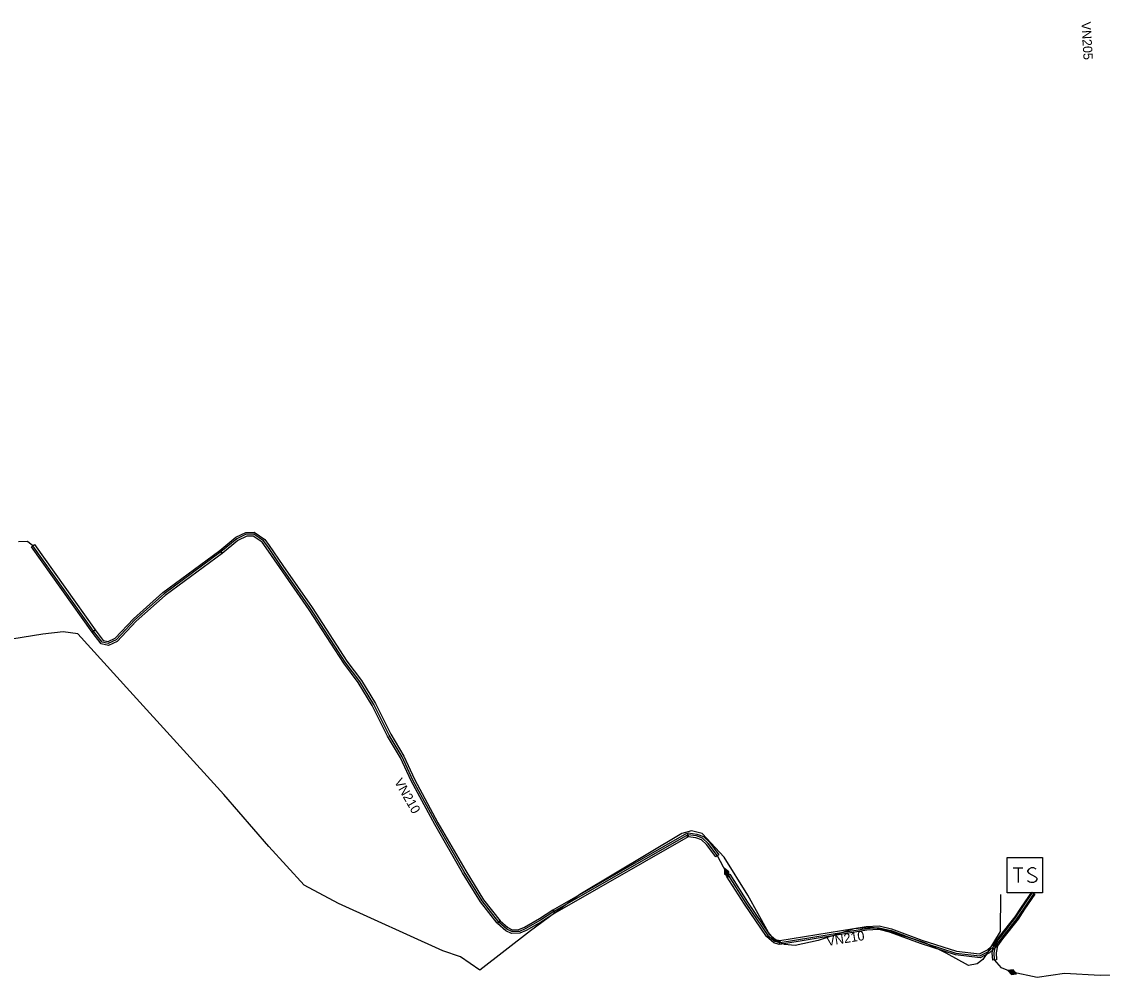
# Model space of a CAD drawing. Extents: x -643811 to -636362, y -1117362 to -1108614.
# Drawn here: x -641784.1 to -641668.7, y -1114810.2 to -1114708.1 of the extents above; entities that cross this region are included whole.
import ezdxf

# ---------------------------------------------------------------- set-up
doc = ezdxf.new("R2010")
doc.units = 0
for name, color, linetype in [('19', 7, 'Continuous'), ('20', 7, 'Continuous'), ('25', 7, 'Continuous'), ('5', 7, 'Continuous'), ('7', 7, 'Continuous'), ('9', 7, 'Continuous')]:
    doc.layers.add(name, color=color, linetype=linetype)

# ---------------------------------------------------------------- blocks, each defined once
blk = doc.blocks.new('VN870')
at = {"layer": '19'}
for points in [[(0, -0.25), (0.5, 0), (0, 0.25), (-0.5, 0), (0, -0.25)], [(0.37, 0), (0, 0.19), (-0.36, 0), (0, -0.19), (0.37, 0)], [(0.24, 0), (0, 0.12), (-0.25, 0), (0, -0.12), (0.24, 0)], [(0.12, 0), (0, 0.06), (-0.13, 0), (0, -0.06), (0.12, 0)]]:
    blk.add_lwpolyline(points, dxfattribs=at)
blk = doc.blocks.new('VN640')
at = {"layer": '25'}
for points in [[(-1.89, 1.89), (1.89, 1.89)], [(-1.89, -1.89), (-1.89, 1.89)], [(1.89, 1.89), (1.89, -1.89)], [(-1.26, 0.79), (-0.22, 0.79)], [(-0.73, 0.79), (-0.73, -0.79)], [(1.2, 0.66), (0.94, 0.79), (0.66, 0.79), (0.41, 0.66), (0.28, 0.47), (0.28, 0.41), (0.41, 0.22), (1.13, -0.16), (1.26, -0.32), (1.26, -0.47), (1.13, -0.66), (0.91, -0.79), (0.63, -0.79), (0.5, -0.73), (0.28, -0.6)], [(1.89, -1.89), (-1.89, -1.89)]]:
    blk.add_lwpolyline(points, dxfattribs=at)

msp = doc.modelspace()

# ---------------------------------------------------------------- linework, layer by layer
at = {"layer": '20'}
for points in [[(-641762.97, -1114764.61), (-641761.25, -1114763.21), (-641760.19, -1114762.69), (-641759.29, -1114762.68), (-641758.16, -1114763.45), (-641757.68, -1114764.09), (-641756.24, -1114766.23), (-641753.1, -1114770.73), (-641749.4, -1114776.45), (-641747.84, -1114778.5), (-641746.34, -1114780.98), (-641744.69, -1114784.26), (-641743.31, -1114786.6), (-641742.18, -1114789.07), (-641739.66, -1114793.71), (-641736.7, -1114798.85), (-641734.79, -1114801.95), (-641733.02, -1114804.19), (-641733.01, -1114804.21), (-641733.17, -1114804.33), (-641733.33, -1114804.45), (-641735.11, -1114802.17), (-641737.04, -1114799.05), (-641740, -1114793.91), (-641742.54, -1114789.25), (-641743.67, -1114786.78), (-641745.05, -1114784.46), (-641746.7, -1114781.18), (-641748.18, -1114778.72), (-641749.72, -1114776.68), (-641753.44, -1114770.95), (-641756.56, -1114766.45), (-641758, -1114764.33), (-641758.44, -1114763.75), (-641759.41, -1114763.08), (-641760.09, -1114763.09), (-641761.03, -1114763.55), (-641762.72, -1114764.93), (-641762.85, -1114764.77), (-641762.98, -1114764.61)], [(-641776.46, -1114773.24), (-641776.62, -1114773.36), (-641783.1, -1114764.23), (-641782.78, -1114763.99), (-641776.3, -1114773.12), (-641776.3, -1114773.12)], [(-641762.97, -1114764.61), (-641762.97, -1114764.61), (-641762.85, -1114764.77), (-641762.73, -1114764.93), (-641768.8, -1114769.43), (-641771.9, -1114772.19), (-641773.92, -1114774.35), (-641774.86, -1114774.77), (-641775.64, -1114774.6), (-641776.62, -1114773.36), (-641776.46, -1114773.24), (-641776.3, -1114773.12), (-641776.3, -1114773.12), (-641775.42, -1114774.24), (-641774.9, -1114774.35), (-641774.16, -1114774.01), (-641772.18, -1114771.91), (-641769.06, -1114769.11)], [(-641727.37, -1114803.02), (-641713.08, -1114794.84), (-641712.98, -1114795.01), (-641712.88, -1114795.18), (-641712.94, -1114795.22), (-641727.17, -1114803.36), (-641727.17, -1114803.36), (-641727.27, -1114803.19)], [(-641712.95, -1114794.81), (-641712.01, -1114794.93), (-641711.29, -1114795.19), (-641710.66, -1114795.79), (-641709.64, -1114797.13), (-641709.96, -1114797.37), (-641710.96, -1114796.05), (-641711.51, -1114795.53), (-641712.11, -1114795.33), (-641712.94, -1114795.22), (-641713.01, -1114795.21), (-641712.98, -1114795.01)], [(-641703.17, -1114806.52), (-641703.22, -1114806.71), (-641703.78, -1114806.55), (-641704.57, -1114805.88), (-641706.92, -1114802.41), (-641708.83, -1114799.43), (-641708.49, -1114799.21), (-641706.59, -1114802.19), (-641704.27, -1114805.61), (-641703.59, -1114806.19), (-641703.15, -1114806.31), (-641703.11, -1114806.33)], [(-641676.22, -1114801.12), (-641675.89, -1114801.34), (-641677, -1114802.96), (-641677.68, -1114804), (-641679.34, -1114806.12), (-641679.89, -1114806.85), (-641679.92, -1114806.89), (-641680.08, -1114806.77), (-641680.08, -1114806.77), (-641680.24, -1114806.65), (-641680.22, -1114806.63), (-641679.66, -1114805.88), (-641678.01, -1114803.76), (-641677.33, -1114802.74)], [(-641733.02, -1114804.19), (-641732.21, -1114804.92), (-641731.72, -1114805.14), (-641731.01, -1114805.13), (-641730.42, -1114804.88), (-641728.82, -1114803.95), (-641727.38, -1114803.02), (-641727.27, -1114803.19), (-641727.16, -1114803.36), (-641727.17, -1114803.36), (-641728.62, -1114804.29), (-641730.24, -1114805.24), (-641730.93, -1114805.53), (-641731.8, -1114805.54), (-641732.43, -1114805.26), (-641733.3, -1114804.48), (-641733.17, -1114804.33), (-641733.04, -1114804.18)], [(-641703.15, -1114806.31), (-641693.9, -1114804.8), (-641692.51, -1114804.73), (-641691.2, -1114805.05), (-641687.97, -1114806.25), (-641684.28, -1114807.44), (-641681.8, -1114807.73), (-641680.97, -1114807.29), (-641680.22, -1114806.63), (-641680.21, -1114806.62), (-641680.08, -1114806.77), (-641680.08, -1114806.77), (-641679.94, -1114806.92), (-641680.39, -1114807.31), (-641680.74, -1114807.62), (-641681.72, -1114808.14), (-641684.37, -1114807.84), (-641688.1, -1114806.63), (-641691.32, -1114805.43), (-641692.55, -1114805.13), (-641693.86, -1114805.2), (-641703.13, -1114806.72), (-641703.17, -1114806.52), (-641703.2, -1114806.32)], [(-641680.27, -1114806.73), (-641680.08, -1114806.77), (-641680.08, -1114806.77), (-641679.88, -1114806.81), (-641679.89, -1114806.85), (-641680.04, -1114807.63), (-641679.99, -1114808.35), (-641680.39, -1114808.38), (-641680.45, -1114807.61), (-641680.39, -1114807.31)]]:
    msp.add_lwpolyline(points, close=True, dxfattribs=at)
at = {"layer": '5'}
for points in [[(-641708.82, -1114799.06), (-641709.8, -1114797.25), (-641710.81, -1114795.92), (-641711.4, -1114795.36), (-641712.06, -1114795.13), (-641712.98, -1114795.01), (-641725.87, -1114802.39), (-641727.27, -1114803.19), (-641728.72, -1114804.12), (-641730.33, -1114805.06), (-641730.97, -1114805.33), (-641731.76, -1114805.34), (-641732.32, -1114805.09), (-641733.17, -1114804.33), (-641734.95, -1114802.06), (-641736.87, -1114798.95), (-641739.83, -1114793.81), (-641742.36, -1114789.16), (-641743.49, -1114786.69), (-641744.87, -1114784.36), (-641746.52, -1114781.08), (-641748.01, -1114778.61), (-641749.56, -1114776.57), (-641753.27, -1114770.84), (-641756.4, -1114766.34), (-641757.84, -1114764.21), (-641758.3, -1114763.6), (-641759.35, -1114762.88), (-641760.14, -1114762.89), (-641761.14, -1114763.38), (-641762.85, -1114764.77), (-641768.93, -1114769.27), (-641772.04, -1114772.05), (-641774.04, -1114774.18), (-641774.88, -1114774.56), (-641775.53, -1114774.42), (-641776.46, -1114773.24), (-641782.94, -1114764.11), (-641783.5, -1114763.67), (-641784.46, -1114763.69)], [(-641708.82, -1114799.06), (-641708.66, -1114799.32), (-641706.76, -1114802.3), (-641704.42, -1114805.75), (-641703.69, -1114806.37), (-641703.17, -1114806.52), (-641703.12, -1114806.51), (-641696.33, -1114805.4), (-641693.88, -1114805), (-641693.07, -1114804.96), (-641692.53, -1114804.93), (-641691.26, -1114805.24), (-641688.49, -1114806.27), (-641688.04, -1114806.44), (-641687.4, -1114806.64), (-641684.33, -1114807.64), (-641681.76, -1114807.94), (-641680.91, -1114807.49), (-641680.86, -1114807.46), (-641680.23, -1114806.91), (-641679.77, -1114806.2), (-641679.58, -1114805.94), (-641677.93, -1114803.82), (-641677.25, -1114802.79), (-641676.14, -1114801.17)], [(-641678.31, -1114809.68), (-641679.47, -1114809.21), (-641680.19, -1114808.37), (-641680.25, -1114807.62), (-641680.11, -1114806.91), (-641679.55, -1114806.23), (-641679.42, -1114806.06), (-641677.77, -1114803.94), (-641677.08, -1114802.9), (-641675.97, -1114801.29)], [(-641664.85, -1114809.98), (-641668.91, -1114810.05), (-641672.74, -1114809.82), (-641675.65, -1114810.24), (-641678.31, -1114809.68)]]:
    msp.add_lwpolyline(points, dxfattribs=at)
at = {"layer": '9'}
msp.add_lwpolyline([(-641679.58, -1114801.37), (-641679.59, -1114805.35), (-641680.91, -1114807.49), (-641680.93, -1114807.53), (-641681.46, -1114808.32), (-641682.06, -1114808.79), (-641682.99, -1114808.98), (-641685.36, -1114807.66), (-641687.4, -1114806.64), (-641687.55, -1114806.57), (-641688.49, -1114806.27), (-641691.62, -1114805.27), (-641693.07, -1114804.96), (-641693.31, -1114804.91), (-641695.22, -1114805.04), (-641696.33, -1114805.4), (-641699.03, -1114806.29), (-641701.49, -1114806.82), (-641702.64, -1114806.73), (-641703.12, -1114806.51), (-641703.71, -1114806.24), (-641704.36, -1114805.43), (-641706.56, -1114801.44), (-641709.09, -1114797.38), (-641711.42, -1114794.88), (-641712.56, -1114794.58), (-641713.6, -1114794.86), (-641724.51, -1114801.38), (-641725.87, -1114802.39), (-641729.76, -1114805.26), (-641735.2, -1114809.45), (-641737.26, -1114808.05), (-641739.16, -1114807.4), (-641750.29, -1114802.35), (-641753.96, -1114800.39), (-641757.75, -1114796.26), (-641762.55, -1114790.69), (-641772.57, -1114779.66), (-641778.14, -1114773.53), (-641779.69, -1114773.32), (-641781.89, -1114773.55), (-641786.3, -1114774.28)], dxfattribs=at)

# ---------------------------------------------------------------- block references
at = {"layer": '19'}
for p, rotation in [((-641708.82, -1114799.06), 117), ((-641678.31, -1114809.68), 158)]:
    msp.add_blockref('VN870', p, dxfattribs=dict(at, rotation=rotation))
at = {"layer": '25'}
msp.add_blockref('VN640', (-641676.95, -1114799.32), dxfattribs=at)

# ---------------------------------------------------------------- texts
at = {"layer": '7'}
for s, rotation, p in [('VN205', 273.4012, (-641670.93, -1114708.17)), ('VN210', 299.9366, (-641744.37, -1114789.33)), ('VN210', 9.2922, (-641698.05, -1114806.89))]:
    msp.add_text(s, height=0.994, rotation=rotation, dxfattribs=at).set_placement(p)

doc.saveas('drawing.dxf')
